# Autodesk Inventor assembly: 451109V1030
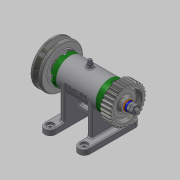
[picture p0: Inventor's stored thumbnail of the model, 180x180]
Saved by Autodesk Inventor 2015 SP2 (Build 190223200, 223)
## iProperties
Created: 2015-11
Part Number: 451109V1030
Document SubType Name: Assembly
Designer: AMC
Author: AMC
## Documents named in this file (16)
- C:\Users\AMC\Desktop\451109V1030\451109V1030.iam
- C:\Users\AMC\Desktop\451109V1030\본체1.ipt
- C:\Users\AMC\Desktop\451109V1030\커버.ipt
- C:\Users\AMC\Desktop\451109V1030\축.ipt
- C:\Users\AMC\Desktop\451109V1030\베어링 15 x 32 x 9.ipt
- C:\Users\AMC\Desktop\451109V1030\오일 실 15 25 7.ipt
- C:\Users\AMC\Desktop\451109V1030\키 3 x 3 x 12.ipt
- C:\Users\AMC\Desktop\451109V1030\V벨트풀리.ipt
- C:\Users\AMC\Desktop\451109V1030\스퍼기어.ipt
- C:\Users\AMC\Desktop\451109V1030\와셔 8x17.ipt
- C:\Users\AMC\Desktop\451109V1030\스프링와셔 8.ipt
- C:\Users\AMC\Desktop\451109V1030\너트 M 8.ipt
- C:\Users\AMC\Desktop\451109V1030\볼트 M4 x 12.ipt
- C:\Users\AMC\Desktop\451109V1030\와셔 6x11.5.ipt
- C:\Users\AMC\Desktop\451109V1030\볼트 M 6 x 8.ipt
- C:\Users\AMC\Desktop\451109V1030\니플 M 6 x 0.75.ipt
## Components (11 placed, 3 different names)
1. KS B 2023 6002 - 15 x 32 x 9:1
2. KS B 2023 6002 - 15 x 32 x 9:2
3. V벨트풀리:1
4. ISO 4762 M4 x 12:1
5. ISO 4762 M4 x 12:2
6. ISO 4762 M4 x 12:3
7. ISO 4762 M4 x 12:4
8. ISO 4762 M4 x 12:5
9. ISO 4762 M4 x 12:6
10. ISO 4762 M4 x 12:7
11. ISO 4762 M4 x 12:8
